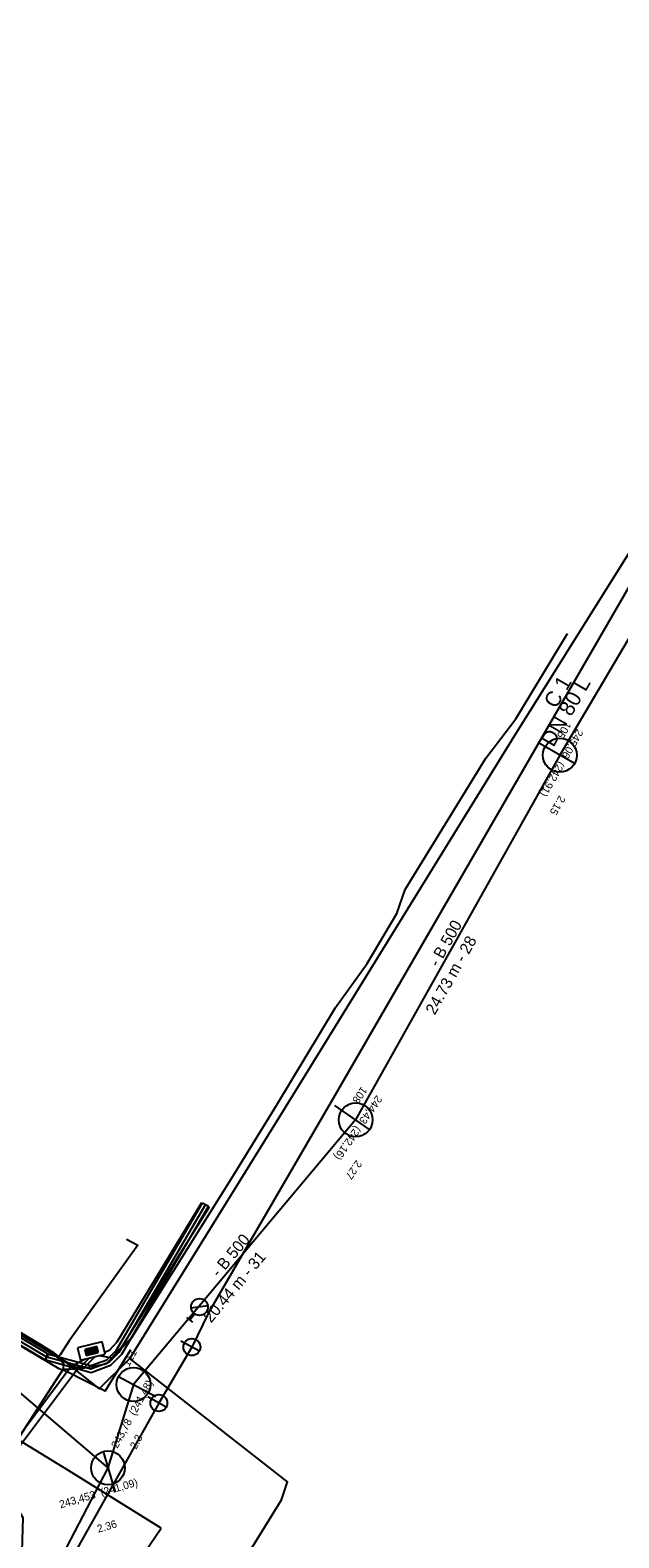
# Model space of a CAD drawing. Extents: x -600636 to -600148, y -1203980 to -1203569.
# Drawn here: x -600244.6 to -600209.8, y -1203728.9 to -1203639.7 of the extents above; entities that cross this region are included whole.
import ezdxf

# ---------------------------------------------------------------- set-up
doc = ezdxf.new("R2010")
doc.units = 0
for name, color, linetype in [('Cetin zam průběh', 7, 'Continuous'), ('EON objekty', 7, 'Continuous'), ('EON podzemní NN', 7, 'Continuous'), ('EON podzemní VN', 7, 'Continuous'), ('GasNet NTL', 7, 'Continuous'), ('Implicitní', 7, 'Continuous'), ('VaK Břeclav_kanalizace', 7, 'Continuous'), ('VaK Břeclav_kanalizace_popis', 7, 'Continuous'), ('Vak Břeclav_vodovod', 7, 'Continuous'), ('Vak Břeclav_vodovod_popis', 7, 'Continuous')]:
    doc.layers.add(name, color=color, linetype=linetype)

# ---------------------------------------------------------------- blocks, each defined once
blk = doc.blocks.new('NN620')
at = {"layer": 'EON objekty'}
for points in [[(0.752, 0.004), (-0.748, 0.004)], [(-0.748, 0.004), (-0.748, -0.746)], [(0.752, -0.746), (0.752, 0.004)], [(-0.748, -0.746), (0.752, -0.746)], [(0.368, -0.18), (-0.376, -0.18)], [(-0.376, -0.18), (-0.376, -0.558)], [(-0.376, -0.558), (0.368, -0.558)], [(0.321, -0.227), (-0.329, -0.227)], [(-0.329, -0.227), (-0.329, -0.51)], [(-0.329, -0.51), (0.321, -0.51)], [(0.274, -0.274), (-0.281, -0.274)], [(-0.281, -0.274), (-0.281, -0.463)], [(-0.281, -0.463), (0.274, -0.463)], [(0.227, -0.321), (-0.234, -0.321)], [(-0.234, -0.321), (-0.234, -0.416)], [(-0.234, -0.416), (0.227, -0.416)], [(-0.193, -0.369), (0.185, -0.369)], [(0.227, -0.416), (0.227, -0.321)], [(0.274, -0.463), (0.274, -0.274)], [(0.321, -0.51), (0.321, -0.227)], [(0.368, -0.558), (0.368, -0.18)]]:
    blk.add_lwpolyline(points, dxfattribs=at)
blk = doc.blocks.new('MoSymbol 2')
at = {"layer": 'Implicitní'}
blk.add_line((0, 0.0005), (0, -0.00075), dxfattribs=at)
blk.add_circle((0, 0), 0.0005, dxfattribs=at)
blk = doc.blocks.new('MoSymbol 3')
at = {"layer": 'Implicitní'}
for p, q in [((-0.000225, 0.00095), (0.000225, 0.00095)), ((0, 0.00095), (0, 0.0005)), ((-0.000365, -0.000365), (0.000365, 0.000365))]:
    blk.add_line(p, q, dxfattribs=at)
blk.add_circle((0, 0), 0.0005, dxfattribs=at)

msp = doc.modelspace()

# ---------------------------------------------------------------- linework, layer by layer
at = {"layer": 'Cetin zam průběh'}
for points in [[(-600238.73, -1203718.32), (-600229.65, -1203703.65), (-600215.97, -1203681.5), (-600208.47, -1203669.5), (-600202.43, -1203659.43), (-600198.13, -1203652.76), (-600191.9, -1203644.36), (-600182.08, -1203632.22), (-600175.22, -1203624.74), (-600171.57, -1203620.8), (-600170.9, -1203620.45), (-600170.66, -1203619.82), (-600162.89, -1203611.32), (-600154.76, -1203602.44), (-600154.39, -1203600.87), (-600148.06, -1203593.79)], [(-600329.02, -1203689.27), (-600327.65, -1203686.16), (-600327.07, -1203683.69), (-600326.94, -1203681.95), (-600327.13, -1203680.22), (-600326.9, -1203679.6), (-600320.9, -1203672.11), (-600319.87, -1203671.25), (-600312.14, -1203676.45), (-600307.68, -1203679.27), (-600299.7, -1203684.11), (-600292.77, -1203688.32), (-600284.45, -1203693.32), (-600273.46, -1203699.98), (-600262.73, -1203706.4), (-600257.97, -1203709.2), (-600243.31, -1203717.93), (-600240.56, -1203720.13), (-600238.73, -1203718.32)], [(-600242.68, -1203718.95), (-600241.74, -1203718.93), (-600240.13, -1203718.64), (-600238.61, -1203717.09), (-600232.73, -1203707.68), (-600230.04, -1203703.32), (-600226.57, -1203697.57), (-600224.69, -1203694.97), (-600222.94, -1203692.01), (-600222.45, -1203690.59), (-600217.67, -1203682.82), (-600215.89, -1203680.49), (-600212.84, -1203675.43)], [(-600232.73, -1203707.68), (-600230.04, -1203703.32)], [(-600257.1, -1203709.7), (-600251.89, -1203712.81), (-600249.32, -1203714.35), (-600243.88, -1203717.57)], [(-600238.94, -1203711.27), (-600238.27, -1203711.62), (-600242.32, -1203717.29), (-600242.86, -1203718.11)], [(-600243.88, -1203717.57), (-600243.03, -1203718.27)], [(-600242.86, -1203718.11), (-600243.03, -1203718.27)], [(-600243.03, -1203718.27), (-600242.67, -1203718.63), (-600242.68, -1203718.95)], [(-600235.23, -1203765.23), (-600240.65, -1203761.08), (-600241.86, -1203760.15), (-600241.91, -1203759.91), (-600241.01, -1203757.3), (-600238.98, -1203751.29), (-600237.59, -1203746.58), (-600234.99, -1203737.4), (-600233.35, -1203732.5), (-600229.76, -1203726.69), (-600229.41, -1203725.62), (-600238.73, -1203718.32)], [(-600242.68, -1203718.95), (-600247.22, -1203725.93), (-600247.46, -1203726.17)], [(-600247.22, -1203725.93), (-600242.68, -1203718.95)]]:
    msp.add_lwpolyline(points, dxfattribs=at)
at = {"layer": 'EON podzemní NN'}
for points in [[(-600240.53, -1203718.154), (-600239.805, -1203718.283), (-600239.168, -1203717.582), (-600234.015, -1203709.363)], [(-600240.224, -1203717.951), (-600239.925, -1203717.821), (-600239.488, -1203717.34), (-600234.484, -1203709.103)], [(-600249.43, -1203714.44), (-600243.42, -1203718), (-600241.94, -1203718.83), (-600241.41, -1203718.82), (-600240.796, -1203718.216)], [(-600241.115, -1203718.296), (-600241.956, -1203719.116), (-600246.209, -1203724.801), (-600246.442, -1203725.59), (-600245.068, -1203727.725), (-600245.152, -1203730.414), (-600245.18, -1203733.274), (-600246.203, -1203734.474), (-600259.048, -1203754.786), (-600265.34, -1203759.062), (-600294.932, -1203798.94), (-600294.8, -1203799.42), (-600294.6, -1203799.71), (-600294.639, -1203800.117), (-600301.927, -1203809.794), (-600302.189, -1203809.81)], [(-600254.356, -1203722.348), (-600253.134, -1203720.313), (-600246.441, -1203724.445), (-600242.224, -1203718.806), (-600241.428, -1203718.369)]]:
    msp.add_lwpolyline(points, dxfattribs=at)
at = {"layer": 'EON podzemní VN'}
msp.add_lwpolyline([(-600234.267, -1203709.224), (-600239.387, -1203717.969), (-600239.987, -1203718.569), (-600241.037, -1203718.959), (-600243.657, -1203718.239), (-600258.967, -1203709.149), (-600259.807, -1203708.439), (-600275.307, -1203699.269), (-600292.687, -1203688.819), (-600307.187, -1203679.949), (-600308.007, -1203680.199), (-600311.007, -1203684.889), (-600311.727, -1203685.219), (-600313.007, -1203684.869), (-600314.967, -1203683.759)], dxfattribs=at)
for points in [[(-600243.759, -1203718.411), (-600259.083, -1203709.312), (-600259.923, -1203708.602), (-600275.409, -1203699.441), (-600292.79, -1203688.99), (-600307.214, -1203680.166), (-600307.948, -1203680.39), (-600308.065, -1203680.008), (-600307.159, -1203679.731), (-600292.583, -1203688.648), (-600275.204, -1203699.097), (-600259.69, -1203708.275), (-600258.85, -1203708.985), (-600243.555, -1203718.067)], [(-600234.441, -1203709.127), (-600234.092, -1203709.321), (-600239.227, -1203718.092), (-600239.876, -1203718.741), (-600241.027, -1203719.169), (-600243.71, -1203718.432), (-600243.604, -1203718.046), (-600241.046, -1203718.749), (-600240.097, -1203718.397), (-600239.546, -1203717.846)]]:
    msp.add_lwpolyline(points, close=True, dxfattribs=at)
at = {"layer": 'GasNet NTL'}
for points in [[(-600240.2, -1203720.25), (-600242.49, -1203719.1), (-600242.92, -1203718.93), (-600251.35, -1203713.94), (-600251.9, -1203713.61), (-600266.36, -1203704.99), (-600266.82, -1203704.7), (-600272.19, -1203701.39), (-600276.83, -1203698.64), (-600283.58, -1203694.63), (-600285.57, -1203693.43), (-600296.81, -1203686.68), (-600301.28, -1203684), (-600307.41, -1203679.95), (-600309.24, -1203678.67), (-600322.08, -1203669.74)], [(-600240.2, -1203720.25), (-600238.68, -1203717.795)]]:
    msp.add_lwpolyline(points, dxfattribs=at)
at = {"layer": 'VaK Břeclav_kanalizace'}
for p, q in [((-600197.304, -1203655.497), (-600213.29, -1203682.64)), ((-600213.29, -1203682.64), (-600225.375, -1203704.212)), ((-600225.375, -1203704.212), (-600238.521, -1203719.864)), ((-600238.521, -1203719.864), (-600240.031, -1203724.796))]:
    msp.add_line(p, q, dxfattribs=at)
for points in [[(-600311.102, -1203679.776), (-600279.472, -1203698.674), (-600250.164, -1203716.186), (-600240.031, -1203724.796)], [(-600240.031, -1203724.796), (-600243.482, -1203731.424), (-600245.022, -1203733.915), (-600249.522, -1203741.19), (-600259.43, -1203757.209), (-600263.646, -1203763.102)]]:
    msp.add_lwpolyline(points, dxfattribs=at)
at = {"layer": 'Vak Břeclav_vodovod'}
for p, q in [((-600234.083, -1203715.623), (-600235.063, -1203717.65)), ((-600235.063, -1203717.65), (-600237.019, -1203720.962))]:
    msp.add_line(p, q, dxfattribs=at)
for points in [[(-600189.723, -1203643.886), (-600209.039, -1203672.378), (-600226.824, -1203703.137), (-600234.083, -1203715.623)], [(-600236.89, -1203728.365), (-600242.377, -1203724.953), (-600264, -1203711.729), (-600288.949, -1203696.473), (-600297.916, -1203690.812), (-600315.791, -1203680.191)], [(-600237.019, -1203720.962), (-600247.043, -1203738.764), (-600258.194, -1203754.202), (-600265.436, -1203763.558), (-600282.474, -1203785.988), (-600297.618, -1203805.864)], [(-600294.521, -1203805.29), (-600277.888, -1203783.466), (-600269.03, -1203771.912), (-600239.859, -1203732.742), (-600236.89, -1203728.365)]]:
    msp.add_lwpolyline(points, dxfattribs=at)

# ---------------------------------------------------------------- block references
at = {"layer": 'EON podzemní NN', "rotation": -166.05044720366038}
msp.add_blockref('NN620', (-600240.919, -1203718.24), dxfattribs=at)
at = {"layer": 'VaK Břeclav_kanalizace'}
for p, xscale, yscale, rotation in [((-600213.29, -1203682.64), 1999.750031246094, 1999.750031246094, -119.87722514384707), ((-600225.375, -1203704.212), 1999.7500312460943, 1999.7500312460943, -124.64247078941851), ((-600238.521, -1203719.864), 1999.7500312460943, 1999.7500312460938, 61.47532664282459), ((-600240.031, -1203724.796), 1999.7500312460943, 1999.7500312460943, 16.311391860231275)]:
    msp.add_blockref('MoSymbol 2', p, dxfattribs=dict(at, xscale=xscale, yscale=yscale, rotation=rotation))
at = {"layer": 'Vak Břeclav_vodovod'}
for name, p, xscale, yscale, rotation in [('MoSymbol 3', (-600234.617, -1203715.281), 999.875015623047, 999.875015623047, 143.3929252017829), ('MoSymbol 2', (-600235.063, -1203717.65), 999.875015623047, 999.875015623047, -118.18387761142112), ('MoSymbol 2', (-600237.019, -1203720.962), 999.8750156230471, 999.8750156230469, -119.97417508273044)]:
    msp.add_blockref(name, p, dxfattribs=dict(at, xscale=xscale, yscale=yscale, rotation=rotation))

# ---------------------------------------------------------------- texts
at = {"layer": 'VaK Břeclav_kanalizace_popis'}
for s, height, rotation, p in [('105', 0.4549, 240.12277, (-600212.982, -1203680.605)), ('245,06  (242,91)', 0.45494, 240.12277, (-600212.271, -1203681.053)), ('2.15', 0.4549, 240.12277, (-600213.323, -1203684.984)), ('- B 500', 0.6824, 60.74171, (-600220.492, -1203695.213)), ('24.73 m - 28', 0.68241, 60.74171, (-600220.691, -1203698.047)), ('108', 0.4549, 235.35753, (-600225.024, -1203702.204)), ('244,43  (242,16)', 0.45494, 235.35753, (-600224.136, -1203702.719)), ('2.27', 0.4549, 235.35753, (-600225.337, -1203706.556)), ('- B 500', 0.6824, 49.97335, (-600233.474, -1203713.572)), ('20.44 m - 31', 0.68241, 49.97335, (-600233.933, -1203716.263)), ('111', 0.4549, 61.47533, (-600238.785, -1203718.849)), ('243,78  (241,48)', 0.45494, 61.47533, (-600239.477, -1203723.675)), ('2.3', 0.4549, 61.47533, (-600238.364, -1203723.729)), ('243,453  (241,09)', 0.45494, 16.31139, (-600242.835, -1203727.191)), ('2.36', 0.4549, 16.31139, (-600240.6, -1203728.636))]:
    msp.add_text(s, height=height, rotation=rotation, dxfattribs=at).set_placement(p)
at = {"layer": 'Vak Břeclav_vodovod_popis'}
for s, p in [('C 1', (-600213.506, -1203679.927)), ('DN 80 L', (-600213.672, -1203682.209))]:
    msp.add_text(s, height=0.9099, rotation=59.9633, dxfattribs=at).set_placement(p)

doc.saveas('drawing.dxf')
